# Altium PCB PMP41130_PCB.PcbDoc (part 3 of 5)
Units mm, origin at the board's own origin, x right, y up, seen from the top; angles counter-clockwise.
Board outline 74.13 x 200.91 mm, 6 copper layers (Top Layer, Layer 1, Inside Layer 1, Inside Layer 2, Layer 2, Bottom Layer), stack 2.208 mm thick; 356 components, 162 nets, 889 pads, 1511 vias.
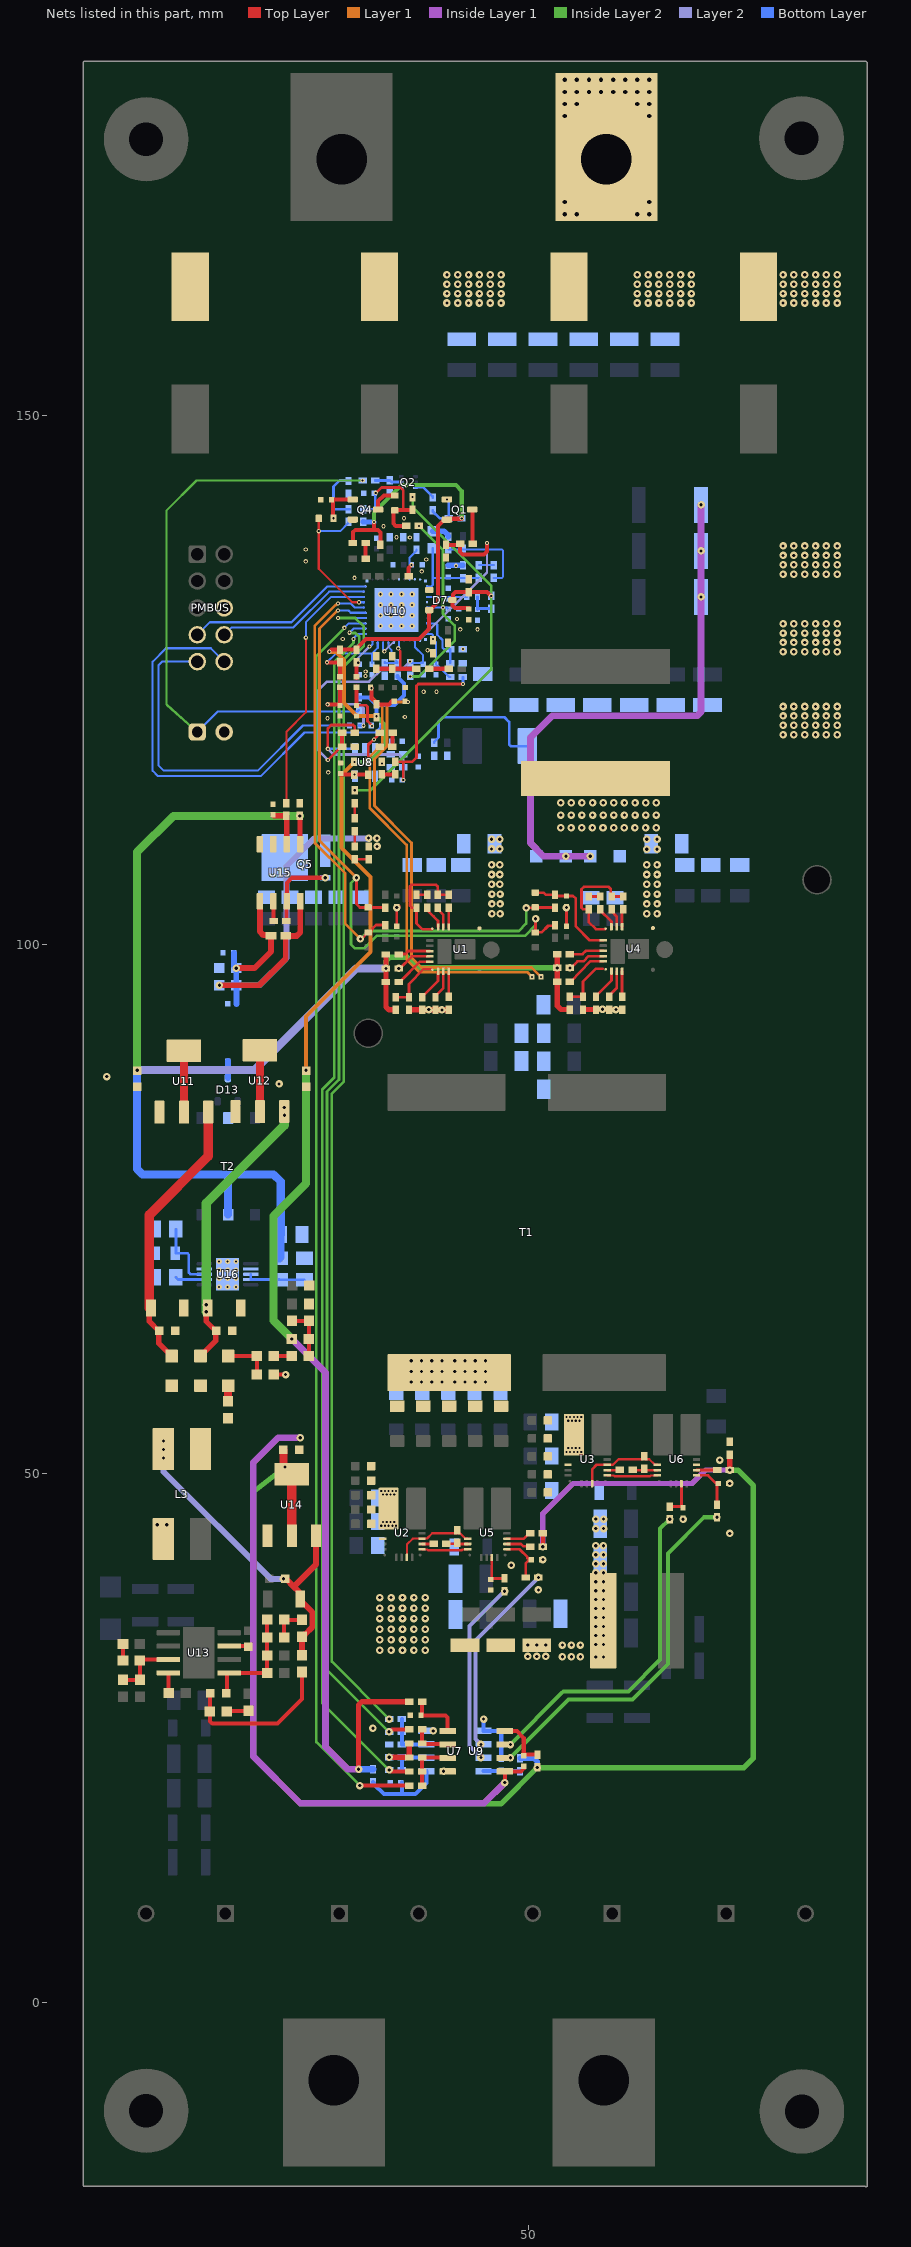
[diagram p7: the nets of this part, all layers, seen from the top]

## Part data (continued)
U1 U4: library part CMP-0120692-1, "100-V, 53-A GaN Half-Bridge Power Stage", Manufacturer="Texas Instruments", Max Supply Voltage=5.25V, Min Supply Voltage=4.75V, Nominal Supply Current=12mA, Operating Temperature Range="-40°C to +125°C"
U2 U3 U5 U6: library part CMP-0037654-1, "100-V, 64-A GaN with Integrated Driver", Manufacturer="Texas Instruments", Max Supply Voltage=5.25V, Min Supply Voltage=4.75V, Nominal Supply Current=3mA, Operating Temperature Range="-40°C to +125°C"
U7 U9: library part CMP-0095064-1, "CAN, RS232, RS485, SPI Digital Isolator 3000Vrms 2 Channel 50Mbps 50kV/µs CMTI 8-SOIC (0.154\", 3.90mm Width)", Digikey Part Number=296-ISO6720BDRCT-ND, Manufacturer="Texas Instruments", Max Supply Voltage=5.5V, Min Supply Voltage=1.71V, Mouser Part Number=595-ISO6720BDR, Operating Temperature Range="-40°C to +125°C"
U8: library part CMP-0032028-2, "CMOS Amplifier 1 Circuit Rail-to-Rail SOT-23-5", Digikey Part Number=296-TLV365DBVRCT-ND, Input Bias Current=0.000005uA, Input Offset Voltage=0.4mV, Manufacturer="Texas Instruments", Max Supply Voltage=5.5V, Min Supply Voltage=2.2V, Mouser Part Number=595-TLV365DBVR, Nominal Supply Current=4.6mA, Operating Temperature Range="-40°C to +125°C", Output Current Per Channel=85mA, Voltage Gain=120dB
U10: library part CMP-04910-000078-1, "DIGITAL CONTROLLER", Max Operating Temperature=125°C, Min Operating Temperature=-40°C
U11 U14: library part CMP-0121358-1, "1-A 16-V high-PSRR linear voltage regulator", Digikey Part Number=296-TLV76150DCYRCT-ND, Dropout Voltage=0.9V, Manufacturer="Texas Instruments", Max Supply Voltage=16V, Min Supply Voltage=6.5V, Mouser Part Number=595-TLV76150DCYR, Nominal Supply Current=65uA, Operating Temperature Range="-40°C to +125°C", Output Voltage=5V
U12: library part CMP-0122558-1, "1-A 16-V high-PSRR linear voltage regulator 4-SOT-223 -40 to 125", Digikey Part Number=296-TLV76133DCYRCT-ND, Dropout Voltage=0.9V, Manufacturer="Texas Instruments", Max Supply Voltage=16V, Min Supply Voltage=4.8V, Mouser Part Number=595-TLV76133DCYR, Nominal Supply Current=65uA, Operating Temperature Range="-40°C to +125°C", Output Voltage=3.3V
U13: library part CMP-0090988-1, "IC", Manufacturer="Texas Instruments", Operating Temperature Range=to
U15: library part CMP-0122620-1, "3kVrms, 5A/5A single-channel isolated gate driver with miller clamp or split out & 8V or 12V UVLO", Digikey Part Number=296-50190-1-ND, Manufacturer="Texas Instruments", Max Power Dissipation=1.14W, Max Supply Voltage=33V, Min Supply Voltage=3V, Mouser Part Number=595-UCC5350SBDR, Operating Temperature Range="-40°C to +125°C"
U16: library part CMP-0092987-2, "Low-Noise 36V Push-Pull Transformer Driver with Duty Cycle Control for Isolated Power Supplies", Manufacturer="Texas Instruments", Operating Temperature Range="-55°C to +150°C"

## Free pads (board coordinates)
  round 2.8 hole 2.5: 2(34.87,91.564) 2(77.274,106.072)

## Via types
v1: diameter 0.711, hole 0.305, Top Layer to Bottom Layer, tented both sides, 1055 vias
v2: diameter 0.457, hole 0.203, Top Layer to Bottom Layer, tented both sides, 161 vias
v3: diameter 0.813, hole 0.406, Top Layer to Bottom Layer, 112 vias
v4: diameter 0.406, hole 0.203, Top Layer to Bottom Layer, tented both sides, 78 vias
v5: diameter 0.61, hole 0.203, Top Layer to Bottom Layer, tented both sides, 71 vias
v6: diameter 0.5, hole 0.2, Top Layer to Bottom Layer, 28 vias
v7: diameter 0.63, hole 0.33, Top Layer to Bottom Layer, 6 vias

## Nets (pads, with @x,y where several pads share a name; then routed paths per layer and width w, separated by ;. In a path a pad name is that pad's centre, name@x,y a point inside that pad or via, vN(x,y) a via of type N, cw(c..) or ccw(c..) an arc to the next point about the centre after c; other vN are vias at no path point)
3V3_SEC: C127.1 D7.2 Q1.2 R40.2 R49.2 R62.2 R67.2 R68.2 R79.2 R91.2 R92.2 R95.2 R103.2 R128.1 R135.2 R136.2 U12.2 U12.4 | length 189.2
  Top Layer w0.381: v4@31.197,127.648 31.376,127.828 R135.2@32.191,127.828 R136.2@33.698,127.828 ; R92.2@33.407,137.918 33.407,138.937 33.631,139.16 35.776,139.16 36.007,138.929 R67.2@36.007,137.848 ; R136.2@33.74,127.828 33.74,127.928 34.637,128.825 39.656,128.825 40.61,129.779 D7.2@40.61,131.56 ; 35.394,139.16 v4(35.394,139.892) ; D7.2@40.827,131.714 41.468,132.355 41.468,139.507 41.982,140.02 42.182,140.02 Q1.2@42.291,140.129 42.369,140.208 43.724,140.208 v4@43.726,140.21
  Top Layer w0.508: v1@33.937,22.007 33.937,28.062 34.274,28.399 R62.2@38.74,28.399
  Top Layer w0.762: U12.2@24.619,84.17 U12.4@24.619,89.97
  Inside Layer 1 w0.635: v1(27.635,62.67) 30.815,59.489 30.815,24.129 32.948,21.996 v1(33.937,21.996)
  Inside Layer 2 w0.381: v4(33.55,117.218) 34.949,117.218 36.412,118.681 36.412,120.779 v4(35.649,121.543) ; v4(35.394,139.892) 35.394,140.782 38.002,143.39 43.154,143.39 43.694,142.849 v4(43.694,140.242)
  Inside Layer 2 w0.762: v1(27.635,62.67) 25.886,64.418 25.886,74.294 28.976,77.383 v1(28.976,88.088)
  Layer 1 w0.381: v1(28.976,88.088) 28.976,93.177 35.076,99.277 35.076,106.342 32.31,109.109 32.31,115.978 v4(33.55,117.218) ; v4(31.182,127.63) 31.788,127.63 32.564,126.853 32.564,122.783 33.804,121.543 v4(35.649,121.543)
  Bottom Layer w0.381: R68.2@33.988,123.332 33.995,123.325 33.995,123.324 34.917,123.324 35.649,122.592 v4@35.649,121.574 ; 35.68,122.592 37.334,122.592 38.256,123.514 38.256,124.631 37.63,125.258 R95.2@37.63,125.358
  Bottom Layer w0.508: R103.2@34.399,139.919 34.412,139.906 35.349,139.906 v4@35.362,139.892
  Bottom Layer w0.635: v1(33.937,21.996) R40.2@35.3,21.996
5V0_PRI: C55.2 C56.2 C131.2 R26.1 R27.1 R41.2 R63.2 U14.2 U14.4 | length 143.4
  Top Layer w0.381: v1(51.358,43.026) 51.363,43.031 R26.1@51.363,43.049 C55.2@51.363,44.3
  Top Layer w0.508: v1(69.028,50.29) C56.2@69.028,51.754
  Top Layer w0.762: U14.4@26.835,50.58 C131.2@26.835,52.199 ; U14.4@27.582,49.886 U14.4@27.635,49.886
  Top Layer w0.889: U14.2@27.635,44.086 U14.4@27.635,49.886
  Inside Layer 1 w0.508: v1(51.358,43.026) 51.358,46.16 54.218,49.02 65.473,49.02 66.743,50.29 v1(69.028,50.29)
  Inside Layer 2 w0.508: v1(26.992,50.577) 24.041,48.26 24.041,23.119 28.43,18.731 47.398,18.731 v1(50.832,22.164) 70.374,22.164 71.266,23.056 71.266,48.814 69.8,50.28 69.038,50.28 v1(69.028,50.29)
  Bottom Layer w0.508: R41.2@49.196,23.028 50.534,23.028 50.832,22.731 v1(50.832,22.164)
5V0_SEC: C8.2 C44.1 C74.2 C147.2 C148.1 R9.2 R14.2 R20.2 R25.2 R34.2 R39.2 R130.2 T2.2 U11.2 U11.4 U15.1 | length 137.5
  Top Layer w0.508: v1(28.392,112.121) 28.409,112.104 28.409,109.473 U15.1@28.427,109.455 ; R9.2@36.533,99.022 v1(36.533,97.697) R20.2@36.533,96.422 36.533,94.077 36.83,93.78 R14.2@37.398,93.781 ; R25.2@52.716,99.056 v1(52.716,97.752) R39.2@52.716,96.456 52.716,94.18 53.08,93.816 R34.2@53.917,93.816
  Top Layer w0.762: U11.2@17.432,84.17 U11.4@17.432,89.92 U11.4@17.432,89.97
  Inside Layer 2 w0.508: v1(36.533,97.697) 36.572,97.736 36.572,98.444 36.869,98.741 38.543,98.741 39.532,97.752 v1(52.716,97.752)
  Inside Layer 2 w0.762: v1(13.012,88.088) 13.012,108.7 16.433,112.121 v1(28.392,112.121)
  Layer 2 w0.762: v1(13.012,88.088) 24.104,88.088 33.713,97.697 v1(36.533,97.697)
  Bottom Layer w0.762: v1(13.012,88.088) 13.012,78.734 13.515,78.23 21.583,78.23 ; T2.2@21.621,74.422 21.621,78.192 21.583,78.23 ; R130.2@26.466,70.302 26.563,70.399 C148.1@26.563,72.547 26.588,72.572 26.588,77.557 25.916,78.23 21.583,78.23
5V_DRI_HB1: C75.1 R12.2 U5.9 | length 2.1
  Top Layer w0.254: R12.2@42.227,43.313 43.181,43.313 C75.1@43.281,43.412 ; C75.1@43.281,43.313 43.294,43.3 U5.9@44.268,43.3
5V_DRI_HB2: C76.1 R13.2 U6.9 | length 2.4
  Top Layer w0.254: R13.2@59.622,50.277 60.771,50.277 C76.1@60.835,50.213 ; C76.1@61.026,50.309 61.054,50.281 U6.9@62.187,50.281
15V0_ACL: C146.2 C150.1 C151.1 C152.1 L4.2 U15.5 | length 14.4
  Top Layer w0.559: v1(22.382,97.729) 24.1,97.729 25.663,99.292 C146.2@25.663,100.777 25.592,100.847 24.944,100.847 24.617,101.175 U15.5@24.617,104.055
  Bottom Layer w0.559: C152.1@22.179,99.163 22.179,97.928 22.374,97.732 C151.1@22.379,97.732 v1(22.382,97.729) 22.382,96.113 C150.1@22.385,96.11 22.385,94.355
AD00: C114.2 R80.1 U10.38 | length 5.5
  Bottom Layer w0.203: U10.38@40.423,130.32 40.425,130.318 41.259,130.318 41.378,130.199 41.378,129.249 41.876,128.75 41.876,128.006 41.995,127.887 C114.2@42.607,127.887 R80.1@42.607,126.565
AD03: C112.1 R76.1 R78.2 U10.5 | length 6.7
  Top Layer w0.203: v4(37.692,127.956) 37.692,127.901 37.876,127.717 37.876,126.029 37.877,126.028
  Top Layer w0.381: C112.1@35.604,126.028 R78.2@37.138,126.028 37.877,126.028 R76.1@39.41,126.028
  Bottom Layer w0.203: v4@37.623,127.887 v4(37.692,127.956) 37.761,128.024 U10.5@37.761,128.67
AGND: C23.1 C24.1 C25.1 C26.1 C27.1 C28.1 C49.2 C50.2 C51.2 C52.2 C57.1 C58.1 C59.1 C60.1 C61.1 C62.1 R54.2 RS1.1 RSENSE1.2 T6.1 | length 13.1
  Bottom Layer w0.254: R54.2@41.087,119.026 41.087,119.126 41.491,119.531 41.491,121.041 41.907,121.457 47.713,121.457 48.178,120.993 48.178,118.861 48.327,118.712 RSENSE1.2@49.888,118.712
  other v1: 74.064,119.799 75.088,119.799 76.111,119.799 77.135,119.799 78.158,119.799 79.182,119.799 74.064,120.686 75.088,120.686 76.111,120.686 77.135,120.686 78.158,120.686 79.182,120.686 74.064,121.574 75.088,121.574 76.111,121.574 77.135,121.574 78.158,121.574 79.182,121.574 74.064,122.462 75.088,122.462 76.111,122.462 77.135,122.462 78.158,122.462 79.182,122.462 74.064,127.628 75.088,127.628 76.111,127.628 77.135,127.628 78.158,127.628 79.182,127.628 74.064,128.516 75.088,128.516 76.111,128.516 77.135,128.516 78.158,128.516 79.182,128.516 74.064,129.404 75.088,129.404 76.111,129.404 77.135,129.404 78.158,129.404 79.182,129.404 74.064,130.292 75.088,130.292 76.111,130.292 77.135,130.292 78.158,130.292 79.182,130.292 74.064,134.971 75.088,134.971 76.111,134.971 77.135,134.971 78.158,134.971 79.182,134.971 74.064,135.858 75.088,135.858 76.111,135.858 77.135,135.858 78.158,135.858 79.182,135.858 74.064,136.746 75.088,136.746 76.111,136.746 77.135,136.746 78.158,136.746 79.182,136.746 74.064,137.634 75.088,137.634 76.111,137.634 77.135,137.634 78.158,137.634 79.182,137.634 42.291,160.602 43.315,160.602 44.338,160.602 45.362,160.602 46.385,160.602 47.409,160.602 60.29,160.602 61.313,160.602 62.337,160.602 63.36,160.602 64.384,160.602 65.408,160.602 74.064,160.602 75.088,160.602 76.111,160.602 77.135,160.602 78.158,160.602 79.182,160.602 42.291,161.49 43.315,161.49 44.338,161.49 45.362,161.49 46.385,161.49 47.409,161.49 60.29,161.49 61.313,161.49 62.337,161.49 63.36,161.49 64.384,161.49 65.408,161.49 74.064,161.49 75.088,161.49 76.111,161.49 77.135,161.49 78.158,161.49 79.182,161.49 42.291,162.378 43.315,162.378 44.338,162.378 45.362,162.378 46.385,162.378 47.409,162.378 60.29,162.378 61.313,162.378 62.337,162.378 63.36,162.378 64.384,162.378 65.408,162.378 74.064,162.378 75.088,162.378 76.111,162.378 77.135,162.378 78.158,162.378 79.182,162.378 42.291,163.265 43.315,163.265 44.338,163.265 45.362,163.265 46.385,163.265 47.409,163.265 60.29,163.265 61.313,163.265 62.337,163.265 63.36,163.265 64.384,163.265 65.408,163.265 74.064,163.265 75.088,163.265 76.111,163.265 77.135,163.265 78.158,163.265 79.182,163.265
  other v3: 53.432,168.998 54.575,168.998 60.29,168.998 61.433,168.998 53.432,170.141 61.433,170.141 53.432,178.269 61.433,178.269 53.432,179.412 54.575,179.412 60.29,179.412 61.433,179.412 53.432,180.555 54.575,180.555 55.718,180.555 56.861,180.555 58.004,180.555 59.147,180.555 60.29,180.555 61.433,180.555 53.432,181.698 54.575,181.698 55.718,181.698 56.861,181.698 58.004,181.698 59.147,181.698 60.29,181.698 61.433,181.698
BP18: C99.2 C100.1 C101.1 U10.28 | length 4.4
  Top Layer w0.381: C99.2@38.761,134.846 C99.2@38.672,134.757 38.672,135.569 v4(38.95,135.847)
  Bottom Layer w0.203: U10.28@38.761,134.483 38.761,136.523 39.412,137.174 C100.1@39.412,137.274
DPWM0A: R44.2 R110.2 U10.11 | length 114.1
  Top Layer w0.381: v1(36.832,21.935) 36.88,21.935 37.03,21.786 R110.2@38.74,21.786
  Inside Layer 2 w0.254: v4(33.462,128.85) 33.462,128.463 31.642,126.643 31.642,87.372 30.506,86.236 30.506,28.261 v1(36.832,21.935)
  Bottom Layer w0.203: v4(33.462,128.85) 33.462,128.905 33.733,129.176 ; 33.733,129.177 33.877,129.32 U10.11@34.611,129.32
DPWM0B: R65.2 R109.2 U10.12 | length 112
  Top Layer w0.381: v1(36.824,25.541) 36.872,25.541 37.104,25.773 R65.2@38.74,25.773
  Inside Layer 2 w0.254: v4(33.082,129.44) 33.112,129.411 33.651,129.411 33.993,129.069 33.993,128.352 32.096,126.455 32.096,87.184 30.96,86.048 30.96,31.405 v1(36.824,25.541)
  Bottom Layer w0.203: v4(33.082,129.44) 33.462,129.82 U10.12@34.611,129.82
DPWM1A: R66.2 U10.13 | length 119.1
  Top Layer w0.381: v1(34.059,20.457) R66.2@38.74,20.457
  Inside Layer 2 w0.254: v4(32.597,129.892) 29.951,127.246 29.951,24.565 v1(34.059,20.457)
  Bottom Layer w0.203: v4(32.597,129.892) 33.025,130.32 U10.13@34.611,130.32
DPWM1B: R45.2 U10.14 | length 112.2
  Inside Layer 2 w0.254: v4(31.992,130.832) 33.624,130.832 34.447,130.009 34.447,128.164 32.55,126.267 32.55,86.996 31.414,85.859 31.414,32.169 v1(36.832,26.751)
  Bottom Layer w0.203: v4(31.992,130.832) 32.001,130.823 34.608,130.823 U10.14@34.611,130.82
DPWM2A: D4.1 D5.1 R43.1 R61.1 U10.15 | length 64.6
  Top Layer w0.254: v1(33.74,106.275) 33.74,103.799 34.068,103.47 D5.1@34.856,103.47 36.454,103.47 R61.1@36.472,103.452 ; D4.1@50.658,101.096 D4.1@50.668,101.106 ; v1(50.677,102.391) 50.668,102.382 D4.1@50.668,101.106 ; R43.1@52.569,101.8 52.507,101.738 51.87,101.738 51.24,101.108 50.67,101.108 D4.1@50.668,101.106
  Inside Layer 2 w0.254: v1(33.74,106.275) 33.232,105.767 33.232,99.982 33.613,99.6 34.472,99.6 35.657,100.785 49.662,100.785 50.677,101.8 v1(50.677,102.391)
  Layer 1 w0.254: v4@31.992,131.528 31.966,131.502 31.912,131.502 30.243,129.833 30.243,109.772 v1(33.74,106.275)
  Bottom Layer w0.203: v4(31.992,131.532) 32.995,131.532 33.206,131.32 U10.15@34.611,131.32
DPWM2B: D3.1 D6.1 R42.1 R64.1 U10.16 | length 60.6
  Top Layer w0.254: v1(34.122,100.491) 34.2,100.491 34.836,101.127 D6.1@34.917,101.127 ; D6.1@34.927,101.117 35.609,101.8 R64.1@36.472,101.8 ; v1(49.782,103.422) 49.806,103.446 50.634,103.446 D3.1@50.658,103.47 52.554,103.47 R42.1@52.569,103.456
  Inside Layer 2 w0.254: v1(34.122,100.491) 34.122,100.508 34.853,101.239 49.092,101.239 49.782,101.93 v1(49.782,103.422)
  Layer 1 w0.254: v4@32.023,132.196 31.946,132.196 31.812,132.062 31.772,132.062 29.789,130.078 29.789,109.584 32.691,106.681 32.691,101.922 v1(34.122,100.491)
  Bottom Layer w0.203: v4(31.992,132.2) 33.198,132.2 33.583,131.816 34.184,131.816 34.187,131.818 34.428,131.818 U10.16@34.431,131.82
DPWM3A: D14.1 R106.1 U10.17 | length 13.6
  Top Layer w0.203: D14.1@30.179,140.242 30.179,135.478 33.336,132.32 v4(33.975,132.32)
  Bottom Layer w0.203: v4(30.179,139.034) 32.202,139.034 32.995,139.828 R106.1@32.995,139.928 ; v4(33.975,132.32) U10.17@34.431,132.32
DPWM3B: R132.1 U10.18 | length 24.3
  Top Layer w0.203: R132.1@27.122,113.321 27.122,120.076 28.959,121.913 v4(28.959,128.97)
  Bottom Layer w0.203: v4(28.959,128.97) 28.959,130.435 31.344,132.82 33.761,132.82 33.766,132.825 34.184,132.825 34.189,132.82 U10.18@34.431,132.82
EAP0: C110.2 C111.1 R75.1 R77.1 U10.31 | length 8.6
  Bottom Layer w0.203: U10.31@40.411,133.82 40.831,133.82 40.95,133.939 40.95,134.716 ; C110.2@40.95,137.434 40.95,134.716 ; 40.97,134.597 40.97,134.696 ; R75.1@45.317,134.622 45.298,134.603 R77.1@43.807,134.603 43.802,134.597 42.431,134.597 41.069,134.597 40.97,134.696 ; 40.95,134.716 40.97,134.696
EAP1: C115.1 FB5.1 U10.33 | length 3.8
  Bottom Layer w0.203: U10.33@40.411,132.82 44.17,132.82 FB5.1@44.179,132.83
EAP2: C113.1 R55.1 R100.1 U10.35 | length 19.9
  Inside Layer 2 w0.254: v4(38.829,125.295) 39.656,125.295 43.026,128.666 43.026,130.111 41.929,131.209 41.929,137.242 v4(39.64,139.531)
  Bottom Layer w0.203: U10.35@40.411,131.82 42.286,131.82 C113.1@42.421,131.685
  other v4: 41.928,131.818
EN_1: J1.1 R68.1 R82.2 | length 58.1
  Inside Layer 2 w0.203: J1.1@18.699,120.052 18.286,120.418 15.835,122.597 15.831,122.601 15.771,122.661 15.771,140.971 18.629,143.829 v4(34.324,143.829)
  Bottom Layer w0.203: J1.1@18.699,120.052 20.635,121.988 31.228,121.988 ; 31.241,121.988 33.844,121.988 R68.1@33.988,122.132
GND: C44.2 C46.2 C82.2 C83.2 C84.2 C88.1 C90.2 C91.2 C92.2 C93.2 C94.2 C95.2 C100.2 C101.2 C102.2 C103.2 C104.2 C105.2 C106.2 C107.2 C108.2 C109.2 C111.2 C112.2 C113.2 C114.1 C115.2 C116.2 C117.2 C118.2 C119.2 C120.2 C121.2 C122.2 C126.2 C127.2 C128.2 C129.2 C139.2 C140.2 C147.1 C148.2 C149.1 C153.1 C154.2 Css1.2 D7.1 J1.2 L3.3 PMBUS.6 Q2.4 Q4.2 R58.1 R59.1 R60.1 R77.2 R78.1 R80.2 R84.1 R94.1 R97.1 R99.2 R104.1 R108.1 R127.1 R131.1 Rlimit1.1 RS1.2 U7.4 U8.2 U9.4 U10.1 U10.6 U10.26 U10.29 U10.30 U10.32 U10.34 U10.36 U10.41 U10.42 U10.43 U10.44 U10.45 U11.1 U12.1 U15.3 U15.4 U16.2 U16.9 U16.11 | length 47
  Top Layer w0.381: C139.2@25.912,59.331 25.92,59.323 27.032,59.323 v1(27.041,59.314)
  Top Layer w0.508: v1(36.832,23.139) 36.844,23.127 38.728,23.127 C94.2@38.74,23.115 C93.2@38.74,24.444 ; v1(41.977,21.815) 41.989,21.803 U9.4@42.37,21.803
  Layer 1 w0.254: v4@38.574,122.91 38.543,122.878 37.048,122.878 36.633,122.463 36.633,118.705 35.445,117.517 35.445,113.079 38.948,109.577 38.948,98.718 39.871,97.795 50.298,97.795 v4(51.189,96.904)
  Bottom Layer w0.508: C111.2@42.431,135.797 42.434,135.8 43.805,135.8 R77.2@43.807,135.803
  other v1: 40.991,25.631 35.3,25.886 14.915,45.125 15.805,45.125 26.431,86.784 10.149,87.483
  other v4: 31.069,116.232 31.006,121.352 38.318,121.46 38.606,122.878 40.09,123.859 41.311,123.859 34.605,125.344 34.608,125.768 40.471,127.78 43.807,127.887 32.441,128.849 43.558,129.749 45.18,129.749 43.253,130.73 33.553,134.622 39.912,135.236 43.154,135.758 28.947,136.18 40.334,136.364 28.955,137.293 38.789,138.435 37.519,138.461 36.294,139.499 38.23,140.257
  other v6: 20.763,67.595 21.563,67.595 22.363,67.595 20.763,68.395 21.563,68.395 22.363,68.395 20.763,69.195 21.563,69.195 22.363,69.195 20.763,69.995 21.563,69.995 22.363,69.995 36.011,130.07 37.011,130.07 38.011,130.07 39.011,130.07 36.011,131.07 37.011,131.07 38.011,131.07 39.011,131.07 36.011,132.07 37.011,132.07 38.011,132.07 39.011,132.07 36.011,133.07 37.011,133.07 38.011,133.07 39.011,133.07
HB1_LS_HI: R29.2 U7.7 | length 17.5
  Layer 2 w0.381: v1(45.508,23.116) 44.427,24.197 44.427,35.529 v1(47.738,38.839)
HB1_LS_HO: U2.2 U5.10 | length 4.4
  Top Layer w0.203: U2.2@39.936,42.8 39.959,42.777 40.436,42.777 40.503,42.711 43.706,42.711 43.767,42.772 U5.10@44.235,42.772
HB1_LS_LI: R31.2 U7.6 | length 18.4
  Layer 2 w0.381: v1(45.508,24.353) 45.008,24.853 45.008,34.194 v1(50.947,40.133)
HB1_MID: C75.2 U2.4 U2.14 U5.8 | length 7.7
  Top Layer w0.203: U2.14@38.511,42.025 38.511,43.25 39.06,43.8 U2.4@39.936,43.8 39.959,43.824 40.412,43.824 40.902,44.314 43.169,44.314 43.249,44.394 43.329,44.314 43.529,44.314 44.043,43.8 U5.8@44.268,43.8
HB2_LS_HI: R30.2 U9.7 | length 31.1
  Inside Layer 2 w0.381: v1(48.291,24.339) 53.145,29.193 53.304,29.352 59.446,29.352 62.457,32.363 62.457,44.744 v1(63.347,45.634)
HB2_LS_HO: U3.2 U6.10 | length 4.8
  Top Layer w0.203: U3.2@57.441,49.781 58.046,49.781 58.12,49.707 61.505,49.707 61.579,49.781 U6.10@62.187,49.781
HB2_LS_LI: R32.2 U9.6 | length 35.1
  Inside Layer 2 w0.381: v1(48.291,23.094) 53.804,28.606 59.845,28.606 63.188,31.95 63.188,42.402 66.611,45.825 v1@67.863,45.825
  other v1: 67.821,45.825
HB2_MID: C76.2 U3.4 U3.14 U6.8 | length 8.1
  Top Layer w0.203: U3.4@57.441,50.781 57.99,50.781 58.52,51.31 60.755,51.31 C76.2@60.835,51.39 ; C76.2@60.962,51.39 61.042,51.31 61.432,51.31 61.962,50.781 U6.8@62.187,50.781
  Top Layer w0.254: U3.14@56.016,49.006 56.016,50.356 56.446,50.786 U3.4@57.432,50.786
HS_Drain: C14.2 C15.2 C16.2 C17.2 C18.2 C19.2 C37.2 C38.2 C39.1 C40.1 C41.1 C42.1 C43.1 C45.1 C47.1 C48.1 C64.2 C65.2 C66.2 C67.2 C68.2 C69.2 C70.2 C71.2 C72.2 C73.2 C123.2 C124.2 L1.2 U2.7 U2.8 U3.7 U3.8 | length 0.3
  Top Layer w0.254: U2.7@36.086,45.023 U2.7@36.414,45.023
  other v1: 56.353,32.618 57.088,32.618 53.211,32.634 54.061,32.634 54.91,32.634 49.936,32.666 50.785,32.666 51.634,32.666 35.937,33.254 37.015,33.254 38.094,33.254 39.172,33.254 40.251,33.254 49.935,33.741 50.784,33.741 51.633,33.741 53.211,33.747 54.061,33.747 54.91,33.747 56.353,33.797 57.088,33.797 35.937,34.25 37.015,34.25 38.094,34.25 39.172,34.25 40.251,34.25 56.353,34.645 57.088,34.645 35.937,35.247 37.015,35.247 38.094,35.247 39.172,35.247 40.251,35.247 56.353,35.493 57.088,35.493 35.937,36.244 37.015,36.244 38.094,36.244 39.172,36.244 40.251,36.244 56.353,36.342 57.088,36.342 56.353,37.19 57.088,37.19 35.937,37.241 37.015,37.241 38.094,37.241 39.172,37.241 40.251,37.241 56.353,38.038 57.088,38.038 35.937,38.238 37.015,38.238 38.094,38.238 39.172,38.238 40.251,38.238 56.353,38.886 57.088,38.886 56.353,39.734 57.088,39.734 56.353,40.582 57.088,40.582 56.353,41.431 57.088,41.431 56.353,42.279 57.088,42.279 56.353,43.127 57.088,43.127 56.363,44.76 57.099,44.76 56.363,45.65 57.099,45.65
  other v2: 36.082,45.023 36.434,45.023 36.786,45.023 37.138,45.023 37.489,45.023 36.258,45.372 36.61,45.372 36.962,45.372 37.314,45.372 36.258,47.968 36.61,47.968 36.962,47.968 37.314,47.968 36.082,48.317 36.434,48.317 36.786,48.317 37.138,48.317 37.489,48.317 53.588,52.006 53.94,52.006 54.292,52.006 54.643,52.006 54.995,52.006 53.764,52.356 54.116,52.356 54.468,52.356 54.819,52.356 53.764,54.951 54.116,54.951 54.468,54.951 54.819,54.951 53.588,55.301 53.94,55.301 54.292,55.301 54.643,55.301 54.995,55.301
NetC1_2: C1.2 C7.2 C9.2 C20.2 C21.2 C22.2 C29.2 C32.2 C53.2 C54.2 T1.1
  other v1: 38.921,58.608 39.889,58.608 40.856,58.608 41.824,58.608 43.044,58.608 44.011,58.608 44.979,58.608 45.947,58.608 38.921,59.613 39.889,59.613 40.856,59.613 41.824,59.613 43.044,59.613 44.011,59.613 44.979,59.613 45.947,59.613 38.921,60.619 39.889,60.619 40.856,60.619 41.824,60.619 43.044,60.619 44.011,60.619 44.979,60.619 45.947,60.619
NetC2_1: C2.1 R11.1 | length 1.1
  Top Layer w0.254: R11.1@39.251,104.655 C2.1@40.337,104.655
NetC2_2: C2.2 U1.10 | length 2.3
  Top Layer w0.254: C2.2@40.337,103.455 40.51,103.282 40.51,103.145 41.027,102.627 41.458,102.196 U1.10@41.458,101.617
NetC3_1: C3.1 C4.1 D1.1 D2.1 R7.1 R8.2 R10.1 | length 52.8
  Inside Layer 1 w0.635: v1(55.836,108.299) v1(53.539,108.299) 51.444,108.299 50.188,109.555 50.188,119.525 52.237,121.574 65.943,121.574 66.315,121.946 v1(66.315,132.815) v1(66.315,137.17) v1(66.315,141.525)
NetC5_1: C5.1 R1.1 R2.1 R3.1
NetC6_1: C6.1 R4.1 R5.1 R6.1
NetC30_1: C30.1 C31.1 R21.1 R22.1 R23.1 R24.1
NetC46_1: C46.1 C126.1 D9.1 U11.3 | length 26.2
  Top Layer w0.508: C46.1@14.171,65.607 14.171,64.328 15.046,63.453 15.071,63.453 15.071,62.267 D9.1@16.271,61.067
  Top Layer w0.889: C46.1@14.171,65.607 14.171,74.402 19.732,79.963 U11.3@19.732,84.12
NetC63_1: C63.1 R28.1 | length 1.1
  Top Layer w0.254: R28.1@55.685,104.503 56.695,104.503 C63.1@56.733,104.466
NetC63_2: C63.2 U4.10 | length 2.2
  Top Layer w0.254: C63.2@56.775,103.303 56.775,103.203 57.846,102.132 U4.10@57.846,101.54
NetC77_1: C77.1 R31.1 U5.2 | length 4.5
  Top Layer w0.254: U5.2@47.968,42.8 49.159,42.8 49.89,42.069 49.89,41.971 C77.1@50.063,41.798 ; R31.1@49.747,40.133 49.747,41.482 C77.1@50.063,41.798 ; C77.1@50.161,41.798 C77.1@50.063,41.798
NetC78_1: C78.1 R32.1 U6.2 | length 4.2
  Top Layer w0.254: U6.2@65.887,49.781 66.967,49.781 C78.1@67.728,49.02 ; R32.1@67.821,47.025 67.821,49.013 C78.1@67.828,49.02
NetC79_1: C79.1 R29.1 U5.14 | length 3.3
  Top Layer w0.254: U5.14@46.543,42.025 46.541,42.023 46.541,40.133 46.448,40.039 R29.1@47.738,40.039
NetC80_1: C80.1 R30.1 U6.14 | length 3.5
  Top Layer w0.254: R30.1@63.352,46.835 64.617,46.835 64.464,46.988 64.464,49.004 U6.14@64.462,49.006
NetC81_1: C81.1 R46.1 R52.2 R56.2 U8.1 | length 33
  Top Layer w0.254: v4(31.038,118.458) 31.038,120.398 31.345,120.706 33.433,120.706 33.582,120.557 R56.2@33.582,120.143 ; R46.1@37.406,117.241 39.023,117.241 39.41,117.627 39.41,124.415 39.591,124.596 v4(43.822,124.596) ; 38.161,117.218 38.169,117.209 v4(38.169,115.506)
  Layer 2 w0.254: v4(31.038,118.458) 31.578,117.917 37.748,117.917 38.156,117.509 38.156,115.52 v4(38.169,115.506)
  Bottom Layer w0.254: v4(31.038,118.458) 33.575,118.458 U8.1@33.601,118.483 ; v4(43.822,124.596) R52.2@43.822,125.232
NetC81_2: C81.2 R47.2 R50.1 U8.4
  other v4: 36.158,117.059
NetC82_1: C82.1 R44.1 U7.2 | length 3.5
  Bottom Layer w0.381: R44.1@38.032,21.935 C82.1@38.032,23.139 38.055,23.116 40.332,23.116 U7.2@40.355,23.094
NetC83_1: C83.1 R45.1 R109.1 U7.3 | length 4.7
  Bottom Layer w0.381: R45.1@38.032,26.751 R109.1@38.032,25.547 C83.1@38.032,24.343 38.042,24.353 40.344,24.353 U7.3@40.355,24.364
NetC84_1: C84.1 R40.1 U7.1 | length 8.2
  Bottom Layer w0.381: R40.1@35.3,20.796 35.41,20.686 35.41,20.586 36.342,19.654 38.01,19.654 ; C84.1@38.032,20.731 38.032,19.676 38.01,19.654 ; U7.1@40.355,21.814 40.355,20.708 39.3,19.654 38.01,19.654
NetC85_1: C85.1 R41.1 U7.8 | length 3.4
  Bottom Layer w0.381: U7.8@45.755,21.824 45.757,21.826 47.427,21.826 47.429,21.828 R41.1@49.196,21.828
NetC88_2: C88.2 R48.1 R49.1 U8.5 | length 2.6
  Top Layer w0.381: C88.2@32.256,116.023 R48.1@34.856,116.023
  other v4: 33.546,116.023
NetC89_1: C89.1 R53.2 R54.1
NetC89_2: C89.2 R50.2 R51.1
NetC91_1: C91.1 R48.2 R53.1 R57.2 U8.3 | length 3.3
  Top Layer w0.254: R48.2@34.856,117.223 34.856,118.845 35.359,119.348 v4(35.394,119.348) 35.68,119.634 35.68,119.823 35.874,120.016 R57.2@35.967,120.016
NetC93_1: C93.1 R65.1 U9.2 | length 3.8
  Top Layer w0.381: R65.1@39.94,25.773 C93.1@39.94,24.444 39.99,24.394 42.32,24.394 U9.2@42.37,24.343
NetC94_1: C94.1 R66.1 R110.1 U9.3 | length 5.1
  Top Layer w0.381: R66.1@39.94,20.457 R110.1@39.94,21.786 C94.1@39.94,23.115 39.96,23.094 42.35,23.094 U9.3@42.37,23.073
NetC95_1: C95.1 R62.1 U9.1 | length 5.1
  Top Layer w0.381: R62.1@39.94,28.399 39.94,27.102 42.147,27.102 42.37,26.879 U9.1@42.37,25.613
NetC96_1: C96.1 R63.1 U9.8 | length 4.9
  Top Layer w0.381: U9.8@47.77,25.613 48.918,25.613 49.554,24.977 49.554,23.384 R63.1@50.851,23.384
NetC107_1: C107.1 FB1.2 FB2.1 | length 8.5
  Top Layer w0.381: v4(31.019,122.66) 32.191,122.66 FB1.2@32.191,124.37
  Layer 2 w0.254: v4(31.019,122.66) 34.054,122.66 34.408,122.306 v4(34.408,120.652)
  Bottom Layer w0.254: FB2.1@33.975,120.667 33.983,120.66 34.401,120.66 v4(34.408,120.652)
NetC109_1: C109.1 FB3.2 FB4.1 | length 4.9
  Top Layer w0.254: C109.1@33.772,122.687 33.868,122.592 34.641,122.592 34.79,122.443 34.79,121.069 35.203,120.656 v4(35.203,120.62)
  Top Layer w0.381: C109.1@33.74,122.687 FB3.2@33.74,124.37
  Bottom Layer w0.254: v4(35.203,120.62) 35.24,120.657 FB4.1@35.24,120.667
NetC110_1: C110.1 R72.1 | length 1.8
  Bottom Layer w0.508: C110.1@40.95,139.034 42.008,139.034 42.431,138.612 R72.1@42.431,138.512
NetC116_1: C116.1 FB5.2 R90.1 | length 2.5
  Bottom Layer w0.254: FB5.2@45.179,132.83 45.184,132.825 45.184,131.631 C116.1@45.188,131.626 ; C116.1@45.188,131.726 45.194,131.721 R90.1@46.478,131.721
NetC117_1: C117.1 D7.3 R88.1 R90.2 R94.2 R101.2 | length 43.6
  Top Layer w0.381: C117.1@44.363,131.77 44.354,131.778 43.041,131.778 42.818,132.002 D7.3@42.818,132.525 42.867,132.574 42.867,133.056 43.091,133.28 R94.2@44.363,133.28 46.102,133.28 46.456,132.926 46.474,132.926 v4(46.478,132.921)
  Inside Layer 2 w0.254: v4(33.582,114.546) 35.076,114.546 46.478,125.949 v4(46.478,132.921) 46.478,133.885 39.051,141.312 v4(39.051,142.277)
NetC119_1: C119.1 FB6.1 R91.1 R99.1 | length 44.1
  Top Layer w0.381: FB6.1@35.172,124.253 v4(35.172,124.182) ; FB6.1@35.173,124.254 v4(35.172,124.182) v4(35.172,124.182) ; C119.1@37.223,122.963 37.123,122.963 36.82,122.66 R91.1@35.63,122.66 35.52,122.77 35.52,122.87 35.172,123.218 v4(35.172,124.182)
  Layer 1 w0.254: v4(35.172,124.182) 35.172,123.419 36.179,122.412 36.179,118.893 34.991,117.705 34.991,112.891 38.494,109.389 38.494,98.53 39.683,97.341 49.902,97.341 v4(50.339,96.904)
NetC122_1: C122.1 D8.2 R100.2 R101.1 R103.1 | length 11.7
  Top Layer w0.254: v4(35.565,142.652) 35.592,142.652 36.107,143.167 37.907,143.167 38.161,142.913 38.161,141.068
  Top Layer w0.381: R100.2@38.44,139.531 37.456,139.531 37.233,139.754 37.233,141.025 37.251,141.042 38.161,141.042 39.022,141.042 R101.1@39.04,141.06
  Bottom Layer w0.254: R103.1@34.399,141.119 35.376,141.119 35.524,141.268 C122.1@35.524,142.629
NetC128_1: C128.1 C129.1 D10.1 U12.3 | length 27.6
  Top Layer w0.508: D10.1@19.006,61.067 20.453,62.514 20.453,63.453 20.429,63.453 19.543,64.338 v1(19.543,65.247)
  Inside Layer 2 w0.889: v1(19.543,65.247) v1(19.543,65.921) 19.543,75.513 26.916,82.885 26.916,83.807 v1(26.935,83.827) 26.927,83.835 26.927,84.55 v1(26.919,84.558)
NetC130_1: C130.1 U13.7 | length 2.1
  Top Layer w0.381: U13.7@21.449,33.661 23.379,33.661 C130.1@23.514,33.526
NetC132_1: C132.1 C135.1 C136.1 L3.2 R115.2 U14.3 | length 32.8
  Top Layer w0.559: C136.1@27.092,39.991 27.821,39.262 ; C132.1@28.607,32.799 R115.2@28.607,34.516 28.607,34.541 28.803,34.737 28.881,34.737 29.562,35.418 29.562,36.87 28.598,37.833 28.598,38.083 28.328,38.354 28.328,38.756 27.821,39.262 ; U14.3@29.935,44.086 29.935,41.376 27.821,39.262
  Layer 2 w0.559: v1(15.508,53.034) v1(15.508,52.228) v1(15.508,51.422) 15.508,50.129 25.631,40.005 v1(26.84,40.005)
NetC132_2: C132.2 C134.1 R116.1 | length 15
  Top Layer w0.381: C134.1@19.888,29.21 19.888,26.538 20.112,26.315 26.27,26.315 28.607,28.652 C132.2@28.607,31.199
NetC133_1: C133.1 R112.1 R117.2 U13.3 | length 5.9
  Top Layer w0.381: R117.2@11.661,30.459 C133.1@13.278,30.459 13.275,30.462 13.275,32.294 13.273,32.297 13.367,32.391 U13.3@15.7,32.391
NetC134_2: C134.2 R118.1 R119.1 R121.2 R122.2 U13.5 | length 10.8
  Top Layer w0.381: U13.5@21.449,31.121 U13.5@21.467,31.104 ; C134.2@21.488,29.21 21.488,31.082 U13.5@21.467,31.104 ; R119.1@25.298,36.143 R122.2@25.298,32.773 R121.2@25.298,31.087 25.281,31.104 U13.5@21.467,31.104
NetC139_1: C139.1 D12.2 R124.1 | length 4.5
  Top Layer w0.381: D12.2@21.612,61.067 21.614,61.069 R124.1@24.326,61.069 ; C139.1@24.312,59.331 24.32,59.339 24.32,61.062 R124.1@24.326,61.069 ; R124.1@24.328,61.071 R124.1@24.326,61.069
NetC141_2: C141.2 C142.2 C143.2 C144.2 C145.2 Q5.5-6-7-8
NetC149_2: C149.2 R130.1 U16.3 U16.4 | length 5.6
  Bottom Layer w0.254: U16.3@23.763,68.795 U16.4@23.763,68.295 26.441,68.295 R130.1@26.466,68.27 C149.2@28.819,68.27
NetC153_2: C153.2 R132.2 U15.2 | length 3.9
  Top Layer w0.508: C153.2@25.852,112.221 25.952,112.121 R132.2@27.122,112.121 ; U15.2@27.157,109.455 R132.2@27.157,112.086
NetC154_1: C154.1 D14.2 Q4.1 R106.2 R108.2 | length 9.9
  Top Layer w0.381: D14.2@31.579,140.242 31.529,140.292 31.529,141.941 31.479,141.991 31.498,142.01 33.369,142.01 Q4.1@33.388,142.029
  Bottom Layer w0.254: v4(31.578,140.261) 31.578,141.094 ; R106.2@33.082,141.119 31.578,141.119 31.578,143.263 31.992,143.676 32.145,143.829 R108.2@33.082,143.829
NetCss1_1: Css1.1 Rlimit1.2 U16.8 | length 6.8
  Bottom Layer w0.254: Rlimit1.2@16.677,73.056 16.677,70.782 17.755,70.782 17.904,70.634 17.904,68.944 18.053,68.795 U16.8@19.363,68.795
NetD8_1: D8.1 Q4.3 | length 2.5
  Top Layer w0.381: Q4.3@35.788,141.079 35.788,141.864 36.348,142.425 D8.1@37.233,142.425
NetD9_2: D9.2 D10.2 L3.1 R123.1
NetD12_1: D12.1 R123.2 | length 1.5
  Top Layer w0.762: R123.2@21.612,56.77 D12.1@21.612,58.267
NetD13_3: D13.3 L4.1 | length 1.6
  Bottom Layer w0.559: D13.3@21.583,87.339 L4.1@21.583,88.955
NetFB2_2: FB2.2 PMBUS.9 | length 33.4
  Bottom Layer w0.203: PMBUS.9@18.699,126.698 15.364,126.698 15.042,126.376 15.042,116.868 15.487,116.423 24.447,116.423 28.691,120.667 FB2.2@33.175,120.667
NetFB4_2: FB4.2 PMBUS.10 | length 42
  Bottom Layer w0.203: PMBUS.10@21.239,126.698 19.971,127.966 15.745,127.966 14.48,126.701 14.48,116.381 14.977,115.883 24.71,115.883 28.831,120.004 35.527,120.004 36.04,120.517 FB4.2@36.04,120.667
NetQ1_1: Q1.1 R79.1 R81.2 | length 3.7
  Bottom Layer w0.254: R81.2@40.95,141.016 40.95,140.916 41.605,140.261 R79.1@42.472,140.261 42.472,141.808 42.291,141.988 v4(42.291,142.029)
NetQ1_3: Q1.3 R83.2 | length 3.2
  Top Layer w0.381: Q1.3@44.691,141.079 44.714,141.057 44.714,137.876 R83.2@44.736,137.854
NetQ2_3: Q2.3 R81.1 | length 2.1
  Bottom Layer w0.254: Q2.3@39.316,143.176 40.09,143.176 40.95,142.316 R81.1@40.95,142.216
NetQ2_5: Q2.5 R82.1 R84.2 | length 2.5
  Bottom Layer w0.254: R82.1@35.524,143.829 R84.2@36.894,143.829 37.047,143.676 Q2.5@37.966,143.676
NetQ5_4: Q5.4 R129.2 U15.7 | length 7.5
  Top Layer w0.381: R129.2@27.02,102.227 R129.2@27.072,102.227 ; R129.2@27.111,102.189 27.134,102.212 27.134,104.032 U15.7@27.157,104.055 27.157,105.8 27.632,106.275 v1(30.783,106.275)
NetR9_1: R9.1 U1.14 | length 3.1
  Top Layer w0.254: R9.1@37.733,99.022 37.78,99.069 38.365,99.069 38.638,99.342 U1.14@40.683,99.342
NetR11_2: R11.2 R18.2 R19.2 U1.11 | length 10.4
  Top Layer w0.254: U1.11@40.908,101.442 40.858,101.392 39.978,101.392 39.423,101.947 R11.2@39.423,103.455 39.42,103.452 38.978,103.452 38.796,103.634 38.796,105.464 38.945,105.613 41.265,105.613 41.414,105.464 R19.2@41.414,104.655 R18.2@42.458,104.655
NetR12_1: R12.1 U2.3 | length 1.1
  Top Layer w0.254: U2.3@39.936,43.3 39.938,43.302 41.013,43.302 R12.1@41.023,43.313
NetR13_1: R13.1 U3.3 | length 0.9
  Top Layer w0.254: U3.3@57.441,50.281 57.443,50.279 58.384,50.279 R13.1@58.386,50.277
NetR14_1: R14.1 R15.1 U1.1 | length 5
  Top Layer w0.254: R14.1@37.462,94.98 38.501,94.98 R15.1@38.511,94.989 ; R15.1@38.711,94.985 38.711,96.238 40.101,97.628 U1.1@40.8,97.628
NetR16_1: R16.1 U1.3 | length 2.6
  Top Layer w0.254: R16.1@41.214,95.09 41.958,95.834 U1.3@41.958,97.417
NetR17_1: R17.1 U1.4 | length 2.4
  Top Layer w0.254: R17.1@42.454,95.053 42.458,95.056 U1.4@42.458,97.417
NetR18_1: R18.1 U1.8 | length 1.8
  Top Layer w0.254: U1.8@42.458,101.617 R18.1@42.458,103.455
NetR19_1: R19.1 U1.9 | length 2.1
  Top Layer w0.254: R19.1@41.361,103.455 41.361,103.355 41.958,102.759 U1.9@41.958,101.617
NetR20_1: R20.1 U1.16 | length 3.7
  Top Layer w0.254: R20.1@37.733,96.422 37.833,96.422 39.753,98.342 U1.16@40.683,98.342
NetR25_1: R25.1 U4.14 | length 3.3
  Top Layer w0.254: R25.1@53.916,99.056 55.103,99.056 55.415,99.367 U4.14@57.074,99.367
NetR26_2: R26.2 U5.3 | length 2.3
  Top Layer w0.254: U5.3@47.968,43.3 49.304,43.3 49.531,43.072 50.14,43.072 R26.2@50.163,43.049
NetR27_2: R27.2 U6.3 | length 1.9
  Top Layer w0.254: U6.3@65.887,50.281 U6.3@65.887,50.281 67.821,50.283 R27.2@67.828,50.29
NetR28_2: R28.2 R37.2 R38.2 U4.11 | length 10.2
  Top Layer w0.254: U4.11@57.273,101.413 56.383,101.413 55.685,102.11 R28.2@55.685,103.303 55.164,103.303 55.015,103.452 55.015,105.197 55.238,105.42 57.591,105.42 57.777,105.234 R38.2@57.777,104.503 ; R38.2@57.787,104.503 R37.2@58.823,104.503
NetR33_1: R33.1 U1.2 | length 3
  Top Layer w0.254: R33.1@39.977,95.049 39.977,95.102 40.133,95.258 40.185,95.258 41.456,96.528 41.456,97.415 U1.2@41.458,97.417
NetR34_1: R34.1 R111.1 U4.1 | length 5
  Top Layer w0.254: R34.1@53.917,95.016 R111.1@55.116,95.016 ; R111.1@55.153,95.016 55.153,96.462 56.351,97.66 57.019,97.66
NetR35_1: R35.1 U4.3 | length 2.6
  Top Layer w0.254: R35.1@57.687,95.116 57.687,95.176 58.349,95.838 U4.3@58.349,97.442
NetR36_1: R36.1 U4.4 | length 2.5
  Top Layer w0.254: U4.4@58.849,97.442 58.851,97.44 58.851,95.002 R36.1@58.863,94.989
NetR37_1: R37.1 U4.8 | length 1.5
  Top Layer w0.254: R37.1@58.8,103.098 58.851,103.047 58.851,101.644 U4.8@58.849,101.642
NetR38_1: R38.1 U4.9 | length 1.9
  Top Layer w0.254: R38.1@57.782,103.289 57.782,103.197 58.349,102.631 U4.9@58.349,101.642
NetR39_1: R39.1 U4.16 | length 4
  Top Layer w0.254: R39.1@53.916,96.456 54.017,96.456 55.828,98.367 U4.16@57.074,98.367
NetR46_2: R46.2 R47.1 | length 1.3
  Top Layer w0.381: R47.1@36.146,116.041 R46.2@37.406,116.041
NetR57_1: R57.1 R59.2 | length 1.4
  Top Layer w0.381: R59.2@37.133,118.641 37.143,118.651 37.143,119.985 R57.1@37.153,119.996
NetR71_1: R71.1 R72.2 R73.2 | length 8.6
  Bottom Layer w0.203: R72.2@42.431,137.312 47.488,137.312 47.607,137.193 47.607,134.741 47.488,134.622 R73.2@46.72,134.622
NetR73_1: R73.1 R75.2 | length 1.4
  Bottom Layer w0.203: R75.2@45.317,135.822 R73.1@46.72,135.822
NetR74_1: R74.1 R76.2 | length 1.9
  Top Layer w0.381: R76.2@40.61,126.028 R74.1@42.475,126.028
NetR85_2: R85.2 R86.1 | length 1.6
  Top Layer w0.254: R86.1@33.585,108.028 33.6,108.012 R85.2@34.79,108.012 ; R85.2@34.733,107.955 R85.2@34.79,108.012 ; R85.2@34.906,108.012 R85.2@34.79,108.012 ; R85.2@34.906,108.128 R85.2@34.79,108.012
NetR86_2: R86.2 R87.1 | length 1.5
  Top Layer w0.254: R86.2@33.585,109.228 R87.1@33.585,110.686
NetR87_2: R87.2 R88.2 | length 1.4
  Top Layer w0.254: R87.2@33.585,111.886 R88.2@33.585,113.331
NetR112_2: R112.2 R113.1 | length 1.6
  Top Layer w0.381: R112.2@11.673,32.297 R113.1@11.673,33.887
NetR114_1: R114.1 R116.2 | length 2.1
  Top Layer w0.381: R116.2@21.488,27.454 21.538,27.503 23.468,27.503 R114.1@23.518,27.553
NetR115_1: R115.1 R118.2 R119.2 | length 3.4
  Top Layer w0.381: R118.2@26.898,34.457 R119.2@26.898,36.143 26.912,36.13 28.594,36.13 R115.1@28.607,36.116
NetR120_2: R120.2 U13.4 | length 2.2
  Top Layer w0.381: U13.4@15.7,31.121 15.935,31.121 15.995,31.062 R120.2@15.995,29.211
NetR124_2: R124.2 R125.1 | length 1.7
  Top Layer w0.381: R124.2@25.928,61.071 25.938,61.061 27.625,61.061 R125.1@27.635,61.052
NetR125_2: R125.2 R126.1 R127.2 R128.2 | length 5
  Top Layer w0.381: R126.1@27.632,64.381 R127.2@29.248,64.381 29.241,64.374 29.241,61.058 R125.2@29.235,61.052
NetR129_1: R129.1 U15.6 | length 1.9
  Top Layer w0.4: U15.6@25.887,104.055 25.899,104.043 25.899,102.201 R129.1@25.911,102.189
NetR131_2: R131.2 U16.7 | length 2.8
  Bottom Layer w0.254: R131.2@16.677,68.509 16.891,68.295 U16.7@19.363,68.295
NetR134_1: R134.1 U4.2 | length 3
  Top Layer w0.254: R134.1@56.415,95.053 56.415,95.141 57.849,96.575 U4.2@57.849,97.442
OCP_Signal: C90.1 R52.1 R58.2 U10.40 | length 5.3
  Bottom Layer w0.203: U10.40@40.411,129.32 40.855,129.32 40.975,129.201 v4(40.975,128.849) 41.253,128.572 C90.1@41.253,126.457 41.451,126.259 41.492,126.259 42.507,125.244 R52.1@42.607,125.244
PAPSU_EN_3138: R83.1 R97.2 U10.8 | length 22.2
  Top Layer w0.381: R97.2@42.201,137.744 43.327,137.744 43.436,137.854 R83.1@43.536,137.854 43.536,137.072 43.76,136.849 45.813,136.849 46.079,137.115 v4(46.079,137.92)
  Layer 2 w0.203: v4(36.384,127.676) 37.558,128.85 39.801,128.85 46.079,135.128 v4(46.079,137.92)
  Bottom Layer w0.203: U10.8@36.261,128.49 36.261,127.854 36.384,127.731 v4(36.384,127.676)
PAPSU_PGOOD: R92.1 R98.2 | length 1.5
  Top Layer w0.381: R98.2@34.607,136.434 R92.1@34.607,137.918
PMBUS_ALT: PMBUS.8 U10.19 | length 14.9
  Bottom Layer w0.203: PMBUS.8@21.239,129.238 21.264,129.238 21.966,129.94 27.797,129.94 31.177,133.32 U10.19@34.431,133.32
PMBUS_CLK: C106.1 FB1.1 R135.1 U10.9 | length 9.5
  Top Layer w0.381: v4@30.955,126.628 R135.1@32.191,126.628 FB1.1@32.191,125.17
  Bottom Layer w0.203: v4@30.942,126.631 30.951,126.631 v4(30.955,126.635) 31.777,127.457 35.214,127.457 ; C106.1@35.214,126.558 35.214,127.457 ; U10.9@35.761,128.49 35.758,128.488 35.758,128.001 35.214,127.457
PMBUS_CTRL: PMBUS.7 U10.20 | length 17.8
  Bottom Layer w0.203: PMBUS.7@18.699,129.238 19.883,130.422 27.6,130.422 30.999,133.82 U10.20@34.611,133.82
PMBUS_DATA: C108.1 FB3.1 R136.1 U10.10 | length 4.2
  Top Layer w0.381: FB3.1@33.74,125.17 R136.1@33.74,126.628
  Layer 2 w0.203: v4(33.912,126.603) 33.912,127.057 v4(34.981,128.125)
  Bottom Layer w0.203: C108.1@34.007,126.558 C108.1@34.084,126.635 ; v4(34.981,128.125) 35.02,128.164 35.079,128.164 35.261,128.346 U10.10@35.261,128.67
PRI_AGND: C55.1 C56.1 C77.2 C78.2 C79.2 C80.2 C85.2 C96.2 C131.1 U5.4 U6.4 U7.5 U9.5 U14.1 | length 70.3
  Top Layer w0.254: U5.4@47.968,43.8 49.563,43.8 50.063,44.3 C55.1@50.163,44.3
  Top Layer w0.381: v1(47.77,20.75) U9.5@47.77,21.803 49.274,21.803 49.554,22.084 C96.2@49.554,22.184
  Inside Layer 1 w0.635: v1(28.435,53.343) 26.344,53.343 23.978,50.977 23.978,23.246 28.43,18.794 45.815,18.794 v1(47.77,20.75)
  Bottom Layer w0.381: v1@45.752,26.751 v1(45.755,26.748) U7.5@45.755,25.634 47.206,25.634 47.429,25.41 C85.2@47.429,23.028
  other v1: 50.947,38.96 48.369,41.277 51.363,41.822 69.028,44.3 64.618,45.64 69.028,49.02 68.086,51.231
RESET: C121.1 R95.1 U10.7 | length 3.6
  Bottom Layer w0.203: C121.1@36.422,126.658 C121.1@36.422,126.558 R95.1@37.63,126.558 37.63,126.658 37.046,127.242 37.046,127.812 36.763,128.094 36.763,128.488 U10.7@36.761,128.49
SCP_Signal: C92.1 R55.2 R56.1 R60.2 U10.2 | length 23.7
  Top Layer w0.254: v4(31.038,117.409) 31.052,117.409 32.285,118.641 R60.2@32.385,118.641
  Top Layer w0.381: R60.2@32.385,118.641 R56.1@32.385,119.996
  Layer 2 w0.254: v4(31.038,117.409) 30.02,118.426 30.02,123.864 30.96,124.804 34.935,124.804 36.189,126.058 38.129,126.058 v4(38.797,126.726)
  Bottom Layer w0.203: R55.2@38.837,126.558 40.045,126.558 40.045,127.293 39.261,128.078 U10.2@39.261,128.67
SR_AGND: C8.1 C74.1 C86.2 C87.2 C97.2 C98.2 R15.2 R16.2 R17.2 R33.2 R35.2 R36.2 R111.2 R134.2 U1.15 U4.15 | length 18.3
  Top Layer w0.254: C98.2@37.557,101.8 C97.2@37.557,103.455 ; C97.2@37.642,103.67 37.642,103.6 37.787,103.455 C97.2@37.787,103.637 ; v1(37.733,97.697) 37.833,97.697 38.978,98.842 U1.15@40.683,98.842 ; C87.2@53.594,101.8 v1(53.594,103.456) ; v1(53.916,97.752) 54.016,97.752 54.631,98.367 55.185,98.367 55.685,98.867 U4.15@57.074,98.867
  Top Layer w0.508: R15.2@38.711,93.785 38.727,93.801 39.96,93.801 39.962,93.799 40.564,93.799 v1(40.578,93.812) 40.592,93.799 41.207,93.799 41.209,93.801 41.227,93.783 41.816,93.783 v1(41.818,93.781) 41.836,93.799 42.44,93.799 R17.2@42.454,93.812 ; R111.2@55.111,93.817 R111.2@55.116,93.822 ; R111.2@55.153,93.816 R134.2@56.39,93.816 R35.2@57.627,93.816 58.86,93.816 R36.2@58.863,93.812
  other v1: 58.273,93.809 57.001,93.841 37.555,103.458
SR_Drain: C5.2 C6.2 C146.1 C150.2 C151.2 C152.2 D1.2 D2.2 L2.1 Q5.1-2-3 R85.1 T2.5 U1.7 U4.7 U15.8 | length 38.9
  Top Layer w0.559: v1(20.785,96.11) 24.563,96.11 27.063,98.61 C146.1@27.063,100.777 28.1,100.777 28.427,101.104 U15.8@28.427,104.055
  Layer 2 w0.559: v1(20.785,96.11) 24.558,96.11 27.126,98.678 27.126,107.36 29.763,109.997 v1@34.945,109.997
  other v1: 46.544,102.879 47.316,102.879 61.185,102.879 62.153,102.879 46.544,103.805 47.316,103.805 61.185,103.805 62.153,103.805 46.544,104.73 47.316,104.73 61.185,104.73 62.153,104.73 46.511,105.656 47.283,105.656 61.185,105.656 62.153,105.656 46.511,106.581 47.283,106.581 61.185,106.581 62.153,106.581 46.511,107.507 47.283,107.507 61.185,107.507 62.153,107.507 61.185,108.965 62.153,108.965 46.511,109 47.283,109 35.686,109.24 46.511,109.919 47.283,109.919 61.185,109.919 62.153,109.919 34.887,110.019 35.682,110.006 53.047,111.006 54.031,111.006 55.037,111.006 56.042,111.006 57.048,111.006 58.054,111.006 59.06,111.006 60.065,111.006 61.071,111.006 62.077,111.006 53.062,112.193 54.045,112.193 55.051,112.193 56.057,112.193 57.062,112.193 58.068,112.193 59.074,112.193 60.08,112.193 61.085,112.193 62.091,112.193 53.061,113.37 54.045,113.37 55.05,113.37 56.056,113.37 57.062,113.37 58.068,113.37 59.073,113.37 60.079,113.37 61.085,113.37 62.091,113.37
SR_GATE1: C86.1 D3.2 R42.2 U4.12 | length 9.8
  Top Layer w0.254: D3.2@50.658,104.87 51.431,104.87 51.645,104.656 R42.2@52.504,104.655 ; R42.2@52.504,104.655 52.603,104.556 54.215,104.556 54.478,104.293 54.478,101.676 55.787,100.367 U4.12@57.074,100.367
